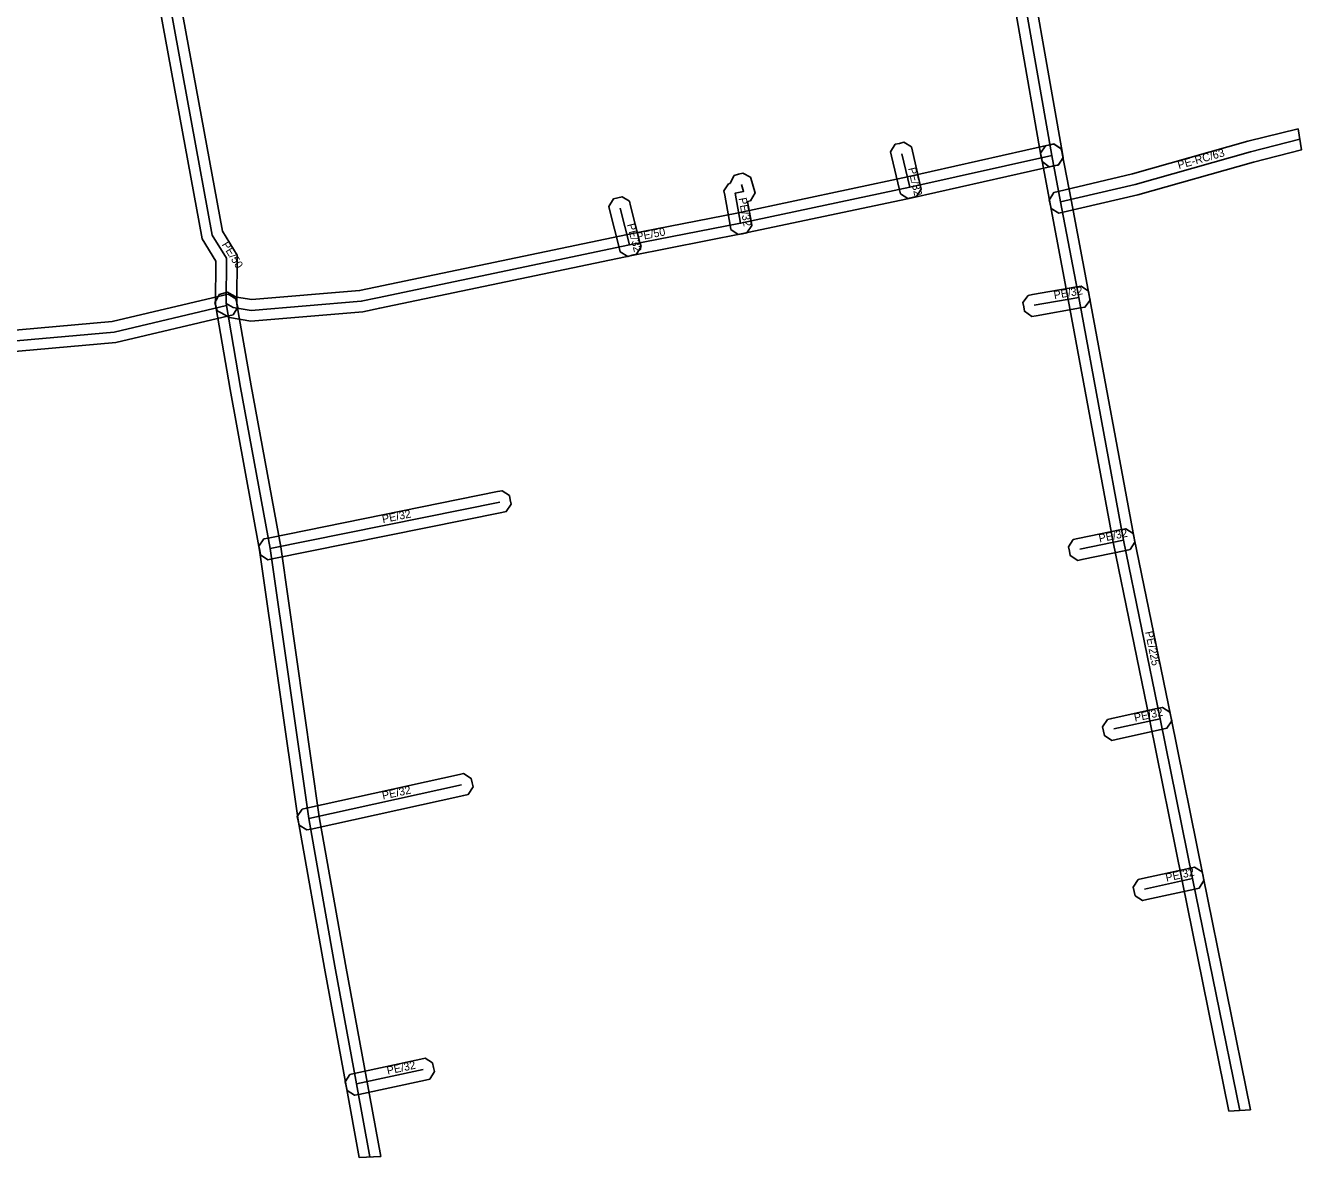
# Model space of a CAD drawing. Extents: x -710999 to -710778, y -1036229 to -1036005.
# Drawn here: x -710897.1 to -710777.6, y -1036223.1 to -1036117 of the extents above; entities that cross this region are included whole.
import ezdxf

# ---------------------------------------------------------------- set-up
doc = ezdxf.new("R2010")
doc.units = 0
for name, color, linetype in [('1', 7, 'Continuous'), ('24', 7, 'Continuous'), ('30', 7, 'Continuous')]:
    doc.layers.add(name, color=color, linetype=linetype)

msp = doc.modelspace()

# ---------------------------------------------------------------- linework, layer by layer
at = {"layer": '1'}
for points in [[(-710886.51, -1036093.45), (-710878.66, -1036136.27), (-710877.27, -1036138.53), (-710877.29, -1036143.03), (-710877.29, -1036143.11), (-710875.97, -1036150.76), (-710873.19, -1036165.84), (-710869.58, -1036191.15), (-710867.13, -1036204.97), (-710865.11, -1036216), (-710863.82, -1036222.96), (-710865.83, -1036223.07), (-710867.07, -1036216.36), (-710869.09, -1036205.33), (-710871.56, -1036191.47), (-710875.17, -1036166.16), (-710877.93, -1036151.1), (-710879.28, -1036143.34), (-710879.29, -1036143.09), (-710879.27, -1036139.09), (-710880.56, -1036136.99), (-710888.47, -1036093.79)], [(-710804.05, -1036105.72), (-710799.96, -1036129), (-710799.89, -1036129.41), (-710800.37, -1036130.08), (-710800.78, -1036130.16), (-710801.19, -1036130.23), (-710801.86, -1036129.75), (-710801.94, -1036129.34), (-710806.02, -1036106.06)]]:
    msp.add_lwpolyline(points, dxfattribs=at)
for points in [[(-710777.86, -1036126.67), (-710777.57, -1036128.66), (-710782.07, -1036129.79), (-710792.91, -1036132.85), (-710799.9, -1036134.49), (-710800.3, -1036134.59), (-710801.01, -1036134.15), (-710801.1, -1036133.75), (-710801.2, -1036133.35), (-710800.76, -1036132.64), (-710800.36, -1036132.55), (-710793.41, -1036130.91), (-710782.59, -1036127.85)], [(-710800.33, -1036130.06), (-710800.73, -1036130.15), (-710814.05, -1036133.13), (-710829.91, -1036136.5), (-710840.31, -1036138.54), (-710863.91, -1036143.48), (-710865.5, -1036143.82), (-710875.99, -1036144.7), (-710877.99, -1036144.37), (-710878.78, -1036143.93), (-710879.14, -1036143.73), (-710879.36, -1036142.94), (-710879.16, -1036142.57), (-710878.96, -1036142.21), (-710878.17, -1036141.98), (-710877.8, -1036142.19), (-710877.33, -1036142.45), (-710875.91, -1036142.68), (-710865.8, -1036141.84), (-710864.33, -1036141.52), (-710840.71, -1036136.58), (-710830.31, -1036134.54), (-710814.47, -1036131.17), (-710801.17, -1036128.19), (-710800.76, -1036128.1), (-710800.07, -1036128.55), (-710799.97, -1036128.95), (-710799.88, -1036129.36)], [(-710815.14, -1036132.78), (-710815.23, -1036132.38), (-710815.96, -1036129.24), (-710816.06, -1036128.83), (-710815.62, -1036128.13), (-710815.22, -1036128.04), (-710814.81, -1036127.94), (-710814.11, -1036128.38), (-710814.02, -1036128.78), (-710813.29, -1036131.92), (-710813.19, -1036132.33), (-710813.63, -1036133.03), (-710814.03, -1036133.12), (-710814.44, -1036133.22)], [(-710782.34, -1036218.61), (-710784.36, -1036218.72), (-710788.75, -1036197.13), (-710791.77, -1036182.16), (-710795.21, -1036165.4), (-710799.41, -1036142.66), (-710801.11, -1036133.71), (-710801.93, -1036129.35), (-710802.01, -1036128.95), (-710801.54, -1036128.26), (-710801.14, -1036128.19), (-710800.73, -1036128.11), (-710800.04, -1036128.58), (-710799.97, -1036128.98), (-710799.15, -1036133.33), (-710797.45, -1036142.3), (-710793.25, -1036165.02), (-710789.81, -1036181.76), (-710786.79, -1036196.73)], [(-710831.23, -1036131.83), (-710831.09, -1036131.8), (-710831.1, -1036131.78), (-710830.7, -1036131.06), (-710830.3, -1036130.94), (-710829.9, -1036130.82), (-710829.18, -1036131.22), (-710829.06, -1036131.62), (-710828.87, -1036132.27), (-710828.75, -1036132.69), (-710828.97, -1036133.06), (-710829.19, -1036133.44), (-710829.46, -1036133.49), (-710829.12, -1036135.34), (-710829.05, -1036135.75), (-710829.52, -1036136.43), (-710829.93, -1036136.51), (-710830.33, -1036136.58), (-710831.02, -1036136.11), (-710831.09, -1036135.7), (-710831.6, -1036132.9), (-710831.68, -1036132.5)], [(-710840.51, -1036133.47), (-710840.41, -1036133.88), (-710839.54, -1036137.32), (-710839.44, -1036137.72), (-710839.86, -1036138.43), (-710840.27, -1036138.53), (-710840.67, -1036138.63), (-710841.38, -1036138.21), (-710841.48, -1036137.81), (-710842.35, -1036134.36), (-710842.45, -1036133.96), (-710842.03, -1036133.25), (-710841.62, -1036133.15), (-710841.22, -1036133.05)], [(-710803.18, -1036142.29), (-710802.77, -1036142.21), (-710798.6, -1036141.49), (-710798.19, -1036141.42), (-710797.52, -1036141.9), (-710797.45, -1036142.31), (-710797.37, -1036142.72), (-710797.85, -1036143.4), (-710798.26, -1036143.46), (-710802.43, -1036144.19), (-710802.84, -1036144.26), (-710803.52, -1036143.78), (-710803.58, -1036143.37), (-710803.66, -1036142.96)], [(-710980.36, -1036153.77), (-710979.95, -1036153.71), (-710967.05, -1036151.86), (-710934.97, -1036148.92), (-710932.04, -1036148.56), (-710888.97, -1036144.73), (-710878.51, -1036142.26), (-710878.11, -1036142.16), (-710877.4, -1036142.6), (-710877.31, -1036143), (-710877.21, -1036143.4), (-710877.65, -1036144.11), (-710878.05, -1036144.2), (-710888.65, -1036146.71), (-710931.83, -1036150.55), (-710934.75, -1036150.9), (-710966.81, -1036153.84), (-710979.67, -1036155.69), (-710980.08, -1036155.75), (-710980.74, -1036155.25), (-710980.8, -1036154.84), (-710980.86, -1036154.43)], [(-710874.78, -1036165.1), (-710874.38, -1036165.02), (-710852.87, -1036160.67), (-710852.46, -1036160.59), (-710851.77, -1036161.05), (-710851.69, -1036161.45), (-710851.61, -1036161.86), (-710852.07, -1036162.55), (-710852.47, -1036162.63), (-710873.98, -1036166.98), (-710874.39, -1036167.06), (-710875.08, -1036166.6), (-710875.16, -1036166.2), (-710875.24, -1036165.79)], [(-710798.94, -1036165.17), (-710798.53, -1036165.08), (-710794.43, -1036164.23), (-710794.03, -1036164.15), (-710793.33, -1036164.6), (-710793.25, -1036165.01), (-710793.17, -1036165.41), (-710793.62, -1036166.1), (-710794.03, -1036166.19), (-710798.13, -1036167.04), (-710798.53, -1036167.12), (-710799.22, -1036166.67), (-710799.31, -1036166.26), (-710799.39, -1036165.86)], [(-710795.75, -1036182.02), (-710795.34, -1036181.93), (-710791, -1036180.98), (-710790.6, -1036180.89), (-710789.9, -1036181.34), (-710789.81, -1036181.75), (-710789.72, -1036182.15), (-710790.17, -1036182.85), (-710790.58, -1036182.94), (-710794.92, -1036183.89), (-710795.32, -1036183.98), (-710796.02, -1036183.53), (-710796.11, -1036183.12), (-710796.2, -1036182.72)], [(-710871.19, -1036190.42), (-710870.79, -1036190.33), (-710856.46, -1036187.18), (-710856.06, -1036187.09), (-710855.36, -1036187.54), (-710855.27, -1036187.95), (-710855.18, -1036188.35), (-710855.63, -1036189.05), (-710856.04, -1036189.14), (-710870.35, -1036192.29), (-710870.76, -1036192.38), (-710871.46, -1036191.93), (-710871.55, -1036191.53), (-710871.64, -1036191.12)], [(-710792.88, -1036197.03), (-710792.47, -1036196.94), (-710787.98, -1036195.95), (-710787.58, -1036195.86), (-710786.88, -1036196.31), (-710786.79, -1036196.71), (-710786.7, -1036197.12), (-710787.15, -1036197.82), (-710787.56, -1036197.91), (-710792.05, -1036198.9), (-710792.45, -1036198.99), (-710793.15, -1036198.54), (-710793.24, -1036198.14), (-710793.33, -1036197.73)], [(-710866.71, -1036215.29), (-710866.3, -1036215.2), (-710860.06, -1036213.85), (-710859.66, -1036213.77), (-710858.96, -1036214.21), (-710858.87, -1036214.62), (-710858.79, -1036215.02), (-710859.23, -1036215.72), (-710859.64, -1036215.81), (-710865.88, -1036217.16), (-710866.28, -1036217.24), (-710866.98, -1036216.8), (-710867.07, -1036216.39), (-710867.16, -1036215.99)]]:
    msp.add_lwpolyline(points, close=True, dxfattribs=at)
at = {"layer": '24'}
for points in [[(-710824.6, -1036005.45), (-710823.8, -1036009.96), (-710823.13, -1036010.81), (-710820.23, -1036029.38), (-710816.01, -1036050.71), (-710813.31, -1036064.52), (-710811.89, -1036071.75), (-710807.19, -1036093.58), (-710805.43, -1036103.62), (-710805.03, -1036105.89), (-710800.95, -1036129.17)], [(-710894.9, -1036052.59), (-710894.43, -1036055.09), (-710894.52, -1036055.47), (-710890.01, -1036078.81), (-710887.49, -1036093.62), (-710879.61, -1036136.63), (-710878.27, -1036138.81), (-710878.29, -1036143.06), (-710878.28, -1036143.23), (-710876.95, -1036150.93), (-710874.18, -1036166), (-710870.57, -1036191.31), (-710868.11, -1036205.15), (-710866.09, -1036216.18), (-710864.83, -1036223.01)], [(-710800.13, -1036133.52), (-710793.16, -1036131.88), (-710782.33, -1036128.82), (-710777.71, -1036127.66)], [(-710800.95, -1036129.17), (-710814.26, -1036132.15), (-710830.11, -1036135.52), (-710840.51, -1036137.56), (-710864.12, -1036142.5), (-710865.65, -1036142.83), (-710875.95, -1036143.69), (-710877.66, -1036143.41), (-710878.29, -1036143.06)], [(-710814.26, -1036132.15), (-710814.99, -1036129.01)], [(-710800.95, -1036129.17), (-710800.13, -1036133.52), (-710798.43, -1036142.48), (-710794.23, -1036165.21), (-710790.79, -1036181.96), (-710787.77, -1036196.93), (-710783.35, -1036218.66)], [(-710830.11, -1036135.52), (-710830.62, -1036132.72), (-710829.83, -1036132.55), (-710830.02, -1036131.9)], [(-710841.38, -1036134.12), (-710840.51, -1036137.56)], [(-710802.6, -1036143.2), (-710798.43, -1036142.48)], [(-710979.81, -1036154.7), (-710966.93, -1036152.85), (-710934.86, -1036149.91), (-710931.93, -1036149.55), (-710888.81, -1036145.72), (-710878.28, -1036143.23)], [(-710874.18, -1036166), (-710852.67, -1036161.65)], [(-710798.33, -1036166.06), (-710794.23, -1036165.21)], [(-710795.13, -1036182.91), (-710790.79, -1036181.96)], [(-710870.57, -1036191.31), (-710856.25, -1036188.16)], [(-710792.26, -1036197.92), (-710787.77, -1036196.93)], [(-710866.09, -1036216.18), (-710859.85, -1036214.83)]]:
    msp.add_lwpolyline(points, dxfattribs=at)

# ---------------------------------------------------------------- texts
at = {"layer": '30'}
for s, rotation, p in [('PE-RC/63', 15.7776, (-710789.05, -1036130.46)), ('PE/32', 283.0879, (-710814.43, -1036130.38)), ('PE/32', 280.3678, (-710830.3, -1036133.19)), ('PE/32', 284.1929, (-710840.75, -1036135.64)), ('PE/50', 11.0735, (-710839.79, -1036137.18)), ('PE/50', 301.5782, (-710878.74, -1036137.52)), ('PE/32', 9.7962, (-710800.71, -1036142.64)), ('PE/32', 11.4328, (-710863.62, -1036163.63)), ('PE/32', 11.7125, (-710796.48, -1036165.44)), ('PE/225', 281.6056, (-710792.22, -1036173.82)), ('PE/32', 12.347, (-710793.16, -1036182.24)), ('PE/32', 12.4059, (-710863.61, -1036189.54)), ('PE/32', 12.4342, (-710790.21, -1036197.23)), ('PE/32', 12.2076, (-710863.17, -1036215.31))]:
    msp.add_text(s, height=0.75, rotation=rotation, dxfattribs=at).set_placement(p)

doc.saveas('drawing.dxf')
